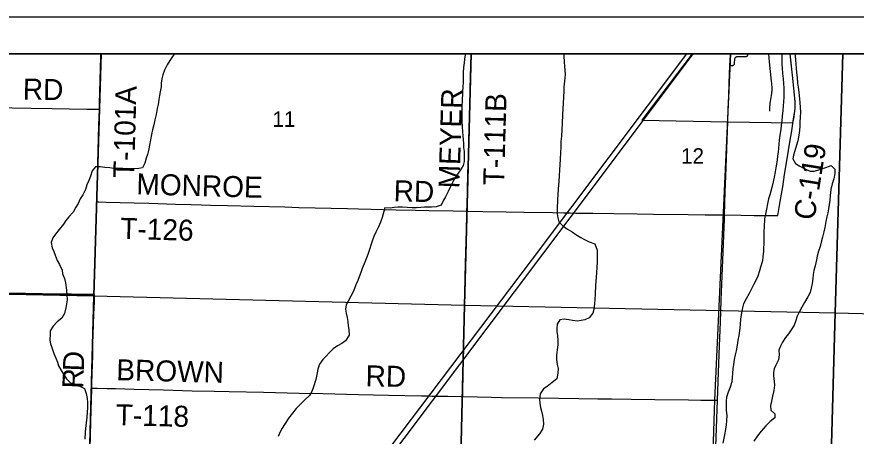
# Model space of a CAD drawing. Extents: x -38.1 to 35.9, y -2.7 to 28.5.
# Drawn here: x 19.827 to 22.099, y 18.696 to 19.831 of the extents above; entities that cross this region are included whole.
import ezdxf

# ---------------------------------------------------------------- set-up
doc = ezdxf.new("R2010")
doc.units = 0
for name, color, linetype in [('GM_X_City_Street', 7, 'Continuous'), ('GM_X_Corporation', 7, 'Continuous'), ('GM_X_Interchange_Ramps', 7, 'Continuous'), ('GM_X_Interstate_Shield', 7, 'Continuous'), ('GM_X_Major_River', 7, 'Continuous'), ('GM_X_Major_River_Text', 7, 'Continuous'), ('GM_X_Minor_Lake', 7, 'Continuous'), ('GM_X_Minor_River', 7, 'Continuous'), ('GM_X_Section', 7, 'Continuous'), ('GM_X_Township', 7, 'Continuous'), ('GM_X_US_Route', 7, 'Continuous'), ('SH_Border', 7, 'Continuous'), ('SH_Data', 7, 'Continuous')]:
    doc.layers.add(name, color=color, linetype=linetype)

msp = doc.modelspace()

# ---------------------------------------------------------------- linework, layer by layer
at = {"layer": 'GM_X_City_Street'}
for points in [[(21.7572, 19.6993), (21.7621, 19.6992), (21.7644, 19.6993), (21.7653, 19.6994), (21.7662, 19.6995), (21.7669, 19.6997), (21.7679, 19.7004), (21.7688, 19.7013), (21.7691, 19.702), (21.7694, 19.7027), (21.7696, 19.7035), (21.7698, 19.7046), (21.77, 19.7059), (21.7705, 19.7153), (21.7706, 19.7167), (21.7709, 19.7179), (21.7713, 19.7192), (21.7718, 19.7201), (21.7724, 19.721), (21.7731, 19.7217), (21.7739, 19.7223), (21.7748, 19.7227), (21.7759, 19.723), (21.7774, 19.7231), (21.7792, 19.7232), (21.7985, 19.723), (21.8007, 19.7231), (21.8015, 19.7233), (21.8025, 19.7237), (21.8033, 19.7242), (21.804, 19.7246), (21.8047, 19.7252), (21.8053, 19.7259), (21.8057, 19.7269), (21.8061, 19.7282), (21.8065, 19.7308)], [(21.8652, 19.5754), (21.8654, 19.584), (21.8656, 19.5883), (21.8659, 19.5925), (21.8664, 19.5969), (21.8672, 19.602), (21.8697, 19.6175), (21.8707, 19.6244), (21.8711, 19.6277), (21.8713, 19.6307), (21.8715, 19.6348), (21.8715, 19.6389), (21.8714, 19.6426), (21.8712, 19.646), (21.8708, 19.6514), (21.8702, 19.6565), (21.8648, 19.709), (21.8627, 19.7308)]]:
    msp.add_lwpolyline(points, dxfattribs=at)
at = {"layer": 'GM_X_Corporation'}
for points in [[(18.6101, 15.7069), (18.8445, 16.0191), (18.9897, 16.2122), (19.0483, 16.2903), (19.2337, 16.5376), (19.4121, 16.7756), (19.566, 16.98), (19.763, 17.2432), (19.9196, 17.4482), (20.1512, 17.7579), (20.6767, 18.4541), (21.2204, 19.1713), (21.641, 19.7308)], [(19.9115, 17.4163), (20.7276, 18.4937), (21.399, 19.3848), (21.6579, 19.7308)], [(25.4101, 13.4873), (25.0847, 13.9186), (24.5478, 14.5412), (23.9622, 15.2897), (23.3945, 15.9977), (22.8429, 16.6968), (22.7771, 16.7664), (22.2793, 17.0387), (22.174, 17.095), (22.1183, 17.1348), (22.0806, 17.1798), (21.9636, 17.4041), (21.7841, 17.7749), (21.744, 17.8537), (21.7155, 17.9287), (21.6978, 17.9866), (21.6921, 18.0413), (21.6956, 18.1468), (21.7163, 18.7934), (21.7602, 19.7303), (21.7602, 19.7308)]]:
    msp.add_lwpolyline(points, dxfattribs=at)
at = {"layer": 'GM_X_Interchange_Ramps'}
for points in [[(21.7572, 19.6993), (21.7587, 19.7278), (21.7589, 19.7308)], [(21.7517, 19.5463), (21.7529, 19.5801), (21.7543, 19.6171), (21.7554, 19.6512), (21.7572, 19.6993)], [(21.7427, 19.2949), (21.7447, 19.3578), (21.7463, 19.4), (21.7517, 19.5463)], [(21.7237, 18.7933), (21.7266, 18.869), (21.7291, 18.9411), (21.7315, 19.0044), (21.7337, 19.0646), (21.738, 19.1727), (21.7423, 19.2832), (21.7427, 19.2949)], [(21.7156, 18.5808), (21.7159, 18.5908), (21.72, 18.692), (21.7218, 18.7436), (21.7237, 18.7933)]]:
    msp.add_lwpolyline(points, dxfattribs=at)
at = {"layer": 'GM_X_Interstate_Shield'}
for points in [[(21.9331, 19.7308), (21.9339, 19.7255), (21.9347, 19.7137), (21.9355, 19.703), (21.9363, 19.6916), (21.9374, 19.6798), (21.9393, 19.6668), (21.9404, 19.6512), (21.942, 19.6406), (21.9439, 19.6272), (21.9447, 19.6177), (21.946, 19.6082), (21.9468, 19.5987), (21.9476, 19.5854), (21.948, 19.5736), (21.9476, 19.5592), (21.9468, 19.5459), (21.9465, 19.5349), (21.9454, 19.5232), (21.9442, 19.5103), (21.9411, 19.4956), (21.9373, 19.4832), (21.929, 19.4568), (21.9275, 19.447), (21.9344, 19.4339), (21.9467, 19.4271), (21.9601, 19.4191), (21.9748, 19.4134), (21.9858, 19.4134), (21.9954, 19.4158), (22.005, 19.4197), (22.0172, 19.4228), (22.0311, 19.4285), (22.041, 19.4183), (22.041, 19.4065), (22.0383, 19.3922), (22.0345, 19.3786), (22.0307, 19.3632), (22.029, 19.3473), (22.0279, 19.3352), (22.0264, 19.3231), (22.0242, 19.311), (22.0223, 19.3008), (22.0197, 19.2895), (22.0171, 19.277), (22.0143, 19.2612), (22.0117, 19.2491), (22.0079, 19.2348), (22.0049, 19.2246), (22.0014, 19.2092), (21.9973, 19.1971), (21.9938, 19.1836), (21.992, 19.173)], [(21.992, 19.173), (21.9881, 19.1575), (21.9847, 19.1447), (21.9828, 19.1338), (21.9814, 19.1228), (21.9798, 19.1092), (21.9776, 19.0967), (21.9746, 19.0854), (21.9685, 19.0735), (21.9593, 19.0582), (21.9521, 19.0455), (21.9449, 19.0316), (21.9392, 19.0208), (21.9346, 19.0069), (21.9313, 18.9963), (21.9253, 18.9863), (21.9158, 18.9733), (21.9079, 18.9632), (21.8992, 18.9506), (21.8939, 18.9401), (21.8898, 18.9292), (21.8902, 18.9167), (21.8886, 18.9027), (21.8818, 18.8885), (21.8773, 18.8787), (21.8751, 18.8689), (21.8752, 18.8594), (21.877, 18.8438), (21.8779, 18.8343), (21.8763, 18.8195), (21.8728, 18.8048), (21.8701, 18.7909), (21.8675, 18.7796), (21.8679, 18.767), (21.8786, 18.7572), (21.8791, 18.7458), (21.8662, 18.7359), (21.8545, 18.7245), (21.8419, 18.7101), (21.8317, 18.6971), (21.8217, 18.683)]]:
    msp.add_lwpolyline(points, dxfattribs=at)
at = {"layer": 'GM_X_Major_River'}
for points in [[(21.7572, 19.6993), (21.7587, 19.7278), (21.7589, 19.7308)], [(21.7517, 19.5463), (21.7529, 19.5801), (21.7543, 19.6171), (21.7554, 19.6512), (21.7572, 19.6993)], [(21.7427, 19.2949), (21.7447, 19.3578), (21.7463, 19.4), (21.7517, 19.5463)], [(21.7237, 18.7933), (21.7266, 18.869), (21.7291, 18.9411), (21.7315, 19.0044), (21.7337, 19.0646), (21.738, 19.1727), (21.7423, 19.2832), (21.7427, 19.2949)], [(21.7156, 18.5808), (21.7159, 18.5908), (21.72, 18.692), (21.7218, 18.7436), (21.7237, 18.7933)]]:
    msp.add_lwpolyline(points, dxfattribs=at)
at = {"layer": 'GM_X_Major_River_Text'}
for points in [[(20.0502, 19.5807), (20.0504, 19.5952), (20.0524, 19.6591), (20.0539, 19.7223), (20.0542, 19.7308)], [(21.0452, 19.3051), (21.0457, 19.3209), (21.0466, 19.3601), (21.0481, 19.4079), (21.0486, 19.4278), (21.0493, 19.4508), (21.0504, 19.4911), (21.0515, 19.534), (21.0519, 19.5551), (21.053, 19.5875), (21.0543, 19.6359), (21.0571, 19.7308)], [(21.928, 19.5429), (21.9308, 19.56), (21.9323, 19.5697), (21.933, 19.5738), (21.9334, 19.5774), (21.9337, 19.5811), (21.9339, 19.5845), (21.9341, 19.588), (21.9342, 19.5913), (21.934, 19.5957), (21.9337, 19.6001), (21.9311, 19.6283), (21.9266, 19.6726), (21.9214, 19.7217), (21.9204, 19.7308)], [(19.04, 19.5971), (19.0466, 19.597), (19.1367, 19.5954), (19.202, 19.5945), (19.2884, 19.5931), (19.3462, 19.5919), (19.3928, 19.5913), (19.44, 19.5906), (19.5121, 19.5896), (19.545, 19.5892), (19.5867, 19.5884), (19.6575, 19.5871), (19.763, 19.5854), (19.866, 19.5838), (19.9226, 19.5828), (20.0167, 19.5813), (20.0502, 19.5807)], [(20.046, 19.4319), (20.047, 19.4689), (20.0489, 19.5366), (20.0502, 19.5807)], [(21.9054, 19.4042), (21.9131, 19.4517), (21.9189, 19.4866), (21.9256, 19.5279), (21.928, 19.5429)], [(20.0433, 19.33), (20.0434, 19.3359), (20.0451, 19.4018), (20.046, 19.4319)], [(21.8873, 19.2933), (21.8936, 19.3312), (21.9001, 19.3706), (21.9054, 19.4042)], [(20.0365, 19.0787), (20.038, 19.1353), (20.0388, 19.1627), (20.0417, 19.2633), (20.0433, 19.33)], [(20.0433, 19.33), (20.0491, 19.3298), (20.0683, 19.3294), (20.1447, 19.3272), (20.1845, 19.3262), (20.2565, 19.3243), (20.2988, 19.3232), (20.3271, 19.3221), (20.3511, 19.3213), (20.3975, 19.3202), (20.4686, 19.3186), (20.5522, 19.3163)], [(20.5522, 19.3163), (20.5901, 19.3153), (20.7224, 19.3123), (20.7522, 19.3116), (20.8541, 19.309), (20.9063, 19.3079), (20.9423, 19.3071), (21.0082, 19.3059), (21.0452, 19.3051)], [(21.0369, 18.9446), (21.0377, 18.9885), (21.0387, 19.0345), (21.0398, 19.0836), (21.0418, 19.1642), (21.0433, 19.2209), (21.0449, 19.2936), (21.0452, 19.3051)], [(21.0452, 19.3051), (21.0883, 19.3041), (21.1511, 19.303), (21.2001, 19.3021), (21.2774, 19.3012), (21.3074, 19.3007), (21.3094, 19.3007)], [(21.3094, 19.3007), (21.325, 19.3003), (21.3402, 19.3), (21.3862, 19.2993), (21.443, 19.2985), (21.5064, 19.2978), (21.5506, 19.2971), (21.6444, 19.2959), (21.69, 19.2953), (21.7368, 19.295), (21.7427, 19.2949)], [(21.7427, 19.2949), (21.7879, 19.2939), (21.823, 19.2935), (21.8873, 19.2933)], [(19.0264, 19.0946), (19.0608, 19.094), (19.1089, 19.0931), (19.1611, 19.0923), (19.2574, 19.0906), (19.3562, 19.0888), (19.4326, 19.0878), (19.4767, 19.0871), (19.5587, 19.086), (19.6656, 19.0844), (19.7246, 19.0835), (19.8508, 19.0817), (19.9415, 19.0804), (19.9612, 19.08)], [(19.9612, 19.08), (19.975, 19.0797), (20.0365, 19.0787)], [(20.0289, 18.8265), (20.0292, 18.8365), (20.0302, 18.8657), (20.0311, 18.8899), (20.0318, 18.9142), (20.0323, 18.9477), (20.0331, 18.9701), (20.0339, 18.9999), (20.0349, 19.026), (20.0361, 19.0602), (20.0365, 19.0787)], [(21.0342, 18.8033), (21.0355, 18.8779), (21.0367, 18.9326), (21.0369, 18.9446)], [(20.0223, 18.5744), (20.0227, 18.5917), (20.0234, 18.6259), (20.0254, 18.6986), (20.0272, 18.7669), (20.0288, 18.8229), (20.0289, 18.8265)], [(20.0289, 18.8265), (20.0447, 18.8262), (20.0712, 18.8256), (20.0938, 18.825), (20.1447, 18.8237), (20.2236, 18.8215), (20.3013, 18.8194), (20.3614, 18.8181), (20.4019, 18.8171), (20.4943, 18.8152), (20.5914, 18.8129), (20.6555, 18.8115), (20.7519, 18.8093), (20.8334, 18.8076), (20.9219, 18.8057), (20.9401, 18.8055), (20.9514, 18.805), (20.9598, 18.8048), (20.9703, 18.8045), (20.9937, 18.8042), (21.0297, 18.8034), (21.0342, 18.8033)], [(21.0342, 18.8033), (21.0735, 18.8025), (21.112, 18.8018), (21.1393, 18.8012), (21.2381, 18.7997), (21.3481, 18.798), (21.3997, 18.7976), (21.4371, 18.7972), (21.4898, 18.7963), (21.5544, 18.7954), (21.6451, 18.7942), (21.6781, 18.7937), (21.7237, 18.7933)]]:
    msp.add_lwpolyline(points, dxfattribs=at)
at = {"layer": 'GM_X_Section'}
for points in [[(20.2537, 19.7308), (20.2485, 19.7232), (20.2406, 19.7128), (20.2334, 19.7012), (20.2262, 19.6866), (20.2223, 19.6735), (20.2198, 19.6629), (20.2179, 19.6508), (20.2172, 19.6413), (20.2153, 19.6281), (20.2135, 19.6179), (20.2113, 19.6074), (20.209, 19.5938), (20.2068, 19.5828), (20.204, 19.5666), (20.2005, 19.5523), (20.1975, 19.5383), (20.1944, 19.5251), (20.1918, 19.5123), (20.1887, 19.4976), (20.186, 19.4832), (20.1829, 19.4689), (20.1803, 19.4587), (20.1773, 19.4482), (20.1735, 19.435), (20.1667, 19.4219), (20.1567, 19.4203), (20.1446, 19.4199), (20.1343, 19.4195), (20.1248, 19.4198), (20.1138, 19.4205), (20.1002, 19.4216), (20.0884, 19.4208), (20.0782, 19.4219), (20.0649, 19.4234), (20.0528, 19.4249), (20.0399, 19.4253), (20.0308, 19.4142), (20.0266, 19.3995), (20.0213, 19.3879), (20.0164, 19.3759), (20.0126, 19.3635), (20.0054, 19.3496), (19.9982, 19.3381), (19.9925, 19.3257), (19.9869, 19.316), (19.9789, 19.3026), (19.9675, 19.2896), (19.9596, 19.2796), (19.9529, 19.2699), (19.9418, 19.2558), (19.9316, 19.2432), (19.9241, 19.2332), (19.9199, 19.2201), (19.9221, 19.206), (19.9271, 19.1956), (19.931, 19.186), (19.9363, 19.1714), (19.9421, 19.1606), (19.9492, 19.1452), (19.9508, 19.1357), (19.9557, 19.1226)], [(21.0402, 19.7308), (21.0402, 19.7278), (21.0391, 19.7164), (21.0381, 19.7066), (21.0361, 19.6933), (21.0354, 19.6801), (21.035, 19.6691), (21.035, 19.6539), (21.0338, 19.6414), (21.0331, 19.6278), (21.0323, 19.6012), (21.0316, 19.5906), (21.0312, 19.5781), (21.0319, 19.5485), (21.0326, 19.534), (21.0337, 19.52), (21.0345, 19.5085), (21.0353, 19.499), (21.0362, 19.4884), (21.0362, 19.477), (21.0374, 19.4667), (21.0382, 19.4534), (21.0378, 19.4397), (21.0351, 19.4281), (21.026, 19.4139), (21.0173, 19.4016), (21.0101, 19.3897), (21.0012, 19.3721), (20.9947, 19.3583), (20.9875, 19.344), (20.9818, 19.3343), (20.9754, 19.3209), (20.962, 19.3167), (20.9494, 19.3159), (20.9399, 19.3162), (20.9304, 19.3157), (20.9201, 19.3149), (20.9087, 19.3137), (20.8973, 19.3137), (20.8833, 19.3148), (20.8708, 19.316), (20.8579, 19.316), (20.848, 19.3151), (20.8373, 19.3135), (20.8232, 19.3139), (20.8156, 19.2876), (20.8111, 19.2748), (20.8058, 19.2624), (20.7989, 19.2478), (20.7936, 19.2362), (20.7895, 19.2261), (20.7858, 19.2156), (20.7812, 19.2013), (20.7773, 19.1877), (20.7728, 19.1757), (20.7667, 19.1622), (20.7618, 19.1502), (20.7581, 19.1394), (20.7539, 19.1277), (20.7502, 19.1176), (20.7449, 19.106), (20.7379, 19.0887), (20.7235, 19.0618), (20.7182, 19.0513), (20.7168, 19.04), (20.7187, 19.0289), (20.7214, 19.0171), (20.723, 19.0064), (20.7241, 18.9946), (20.7254, 18.9851), (20.7265, 18.9699), (20.7169, 18.9538), (20.7064, 18.9469), (20.6948, 18.9404), (20.6836, 18.9328), (20.6726, 18.9221), (20.6647, 18.9125), (20.655, 18.9033), (20.6463, 18.8914), (20.6413, 18.8775), (20.6399, 18.8677), (20.6363, 18.8496), (20.6295, 18.827), (20.6254, 18.8169), (20.6187, 18.8068)], [(21.3081, 19.7308), (21.3079, 19.7242), (21.3085, 19.7086), (21.3097, 19.6964), (21.3105, 19.6861), (21.311, 19.6747), (21.3093, 19.6569), (21.308, 19.6403), (21.3074, 19.63), (21.3069, 19.6145), (21.306, 19.5963), (21.3052, 19.5823), (21.3039, 19.5656), (21.3033, 19.5432), (21.302, 19.5251), (21.3011, 19.5076), (21.2999, 19.4936), (21.2995, 19.4781), (21.2983, 19.4633), (21.2974, 19.4455), (21.2969, 19.4299), (21.2957, 19.4171), (21.2949, 19.4008), (21.2937, 19.3852), (21.2919, 19.3655), (21.2911, 19.35), (21.2903, 19.336), (21.2896, 19.3113), (21.2896, 19.2977), (21.2911, 19.2866), (21.2942, 19.2759), (21.3049, 19.265), (21.3176, 19.2562), (21.3299, 19.2487), (21.34, 19.2423), (21.3538, 19.2339), (21.3635, 19.2283), (21.3758, 19.2219), (21.3912, 19.2162), (21.398, 19.1996), (21.3982, 19.1841), (21.3981, 19.1677), (21.3973, 19.1522), (21.3961, 19.1386), (21.3954, 19.1265), (21.3943, 19.1147), (21.3936, 19.1045), (21.3929, 19.0806), (21.3917, 19.0658), (21.3906, 19.0549), (21.3886, 19.0394), (21.3864, 19.0292), (21.3766, 19.0162), (21.3646, 19.0112), (21.3543, 19.0089), (21.3444, 19.0076), (21.3308, 19.0088), (21.321, 19.0113), (21.3089, 19.0132), (21.2967, 19.0113), (21.2895, 18.9994), (21.2888, 18.9887), (21.2889, 18.9785), (21.2901, 18.9686), (21.2912, 18.9538), (21.2912, 18.9435), (21.2893, 18.9299), (21.2874, 18.9155), (21.2874, 18.9034), (21.2897, 18.8904), (21.292, 18.8797), (21.2913, 18.8672), (21.2889, 18.8517), (21.276, 18.8411), (21.2621, 18.8309), (21.2524, 18.824), (21.2432, 18.8106), (21.242, 18.7954), (21.2425, 18.7859), (21.2448, 18.7741), (21.2476, 18.7638), (21.2495, 18.7519), (21.2518, 18.7412), (21.2526, 18.7291), (21.2495, 18.7151), (21.2419, 18.7024), (21.2274, 18.6858)], [(21.8976, 19.7308), (21.8975, 19.7276), (21.8977, 19.7109), (21.8978, 19.7014), (21.8983, 19.6919), (21.8994, 19.6775), (21.9013, 19.6634), (21.9024, 19.6504), (21.9032, 19.6375), (21.9036, 19.6257), (21.9028, 19.6132), (21.9021, 19.6007), (21.9018, 19.5901), (21.9002, 19.5769), (21.8983, 19.5621), (21.8975, 19.5504), (21.8964, 19.5375), (21.8949, 19.5258), (21.8926, 19.5106), (21.891, 19.4974), (21.89, 19.4864), (21.8889, 19.4751), (21.8878, 19.4645), (21.8863, 19.4543), (21.8853, 19.4433), (21.8834, 19.4331), (21.8816, 19.4218), (21.8801, 19.4112), (21.8774, 19.3968), (21.8748, 19.384), (21.8705, 19.3693), (21.868, 19.3591), (21.865, 19.3493), (21.862, 19.338), (21.8594, 19.3252), (21.8563, 19.3101), (21.8532, 19.2965), (21.8509, 19.2845), (21.8503, 19.2625), (21.8495, 19.25), (21.8492, 19.2401), (21.8492, 19.2257), (21.8483, 19.1969), (21.8468, 19.1817), (21.8457, 19.1704), (21.8398, 19.1531), (21.8373, 19.1433), (21.8327, 19.129), (21.827, 19.1174), (21.821, 19.1054), (21.8161, 19.0953), (21.8093, 19.0826), (21.8016, 19.068), (21.7944, 19.0546), (21.7914, 19.0433), (21.7878, 19.0251), (21.7863, 19.0127), (21.7848, 18.999), (21.7837, 18.9884), (21.7812, 18.9688), (21.7785, 18.9556), (21.7766, 18.9427), (21.7739, 18.9269), (21.7713, 18.9167), (21.769, 18.9038), (21.7667, 18.8906), (21.7656, 18.8785), (21.7645, 18.8656), (21.7634, 18.855), (21.7623, 18.8437), (21.7577, 18.8286), (21.7527, 18.8155), (21.7482, 18.802), (21.7471, 18.791), (21.7467, 18.78), (21.7475, 18.7659), (21.7486, 18.7522), (21.7482, 18.7378), (21.7471, 18.7272), (21.7456, 18.7151), (21.7434, 18.7042), (21.738, 18.677)], [(19.9557, 19.1226), (19.9588, 19.1111), (19.9609, 19.091), (19.962, 19.078), (19.9628, 19.0651), (19.9613, 19.0545), (19.9591, 19.0436), (19.956, 19.0285), (19.9488, 19.0158), (19.9363, 19.0052), (19.925, 18.9941), (19.9174, 18.9814), (19.9167, 18.9716), (19.9166, 18.956), (19.9182, 18.9465), (19.9214, 18.9362), (19.9266, 18.9197), (19.9323, 18.907), (19.9369, 18.8966), (19.94, 18.8867), (19.9461, 18.8755), (19.9545, 18.8619), (19.9614, 18.8515), (19.9717, 18.8406), (19.9855, 18.8333), (19.9977, 18.8318), (20.01, 18.8254), (20.0145, 18.812), (20.0168, 18.7979), (20.018, 18.7872), (20.0179, 18.7732), (20.0176, 18.761), (20.0164, 18.7478), (20.0145, 18.7323), (20.0129, 18.7168), (20.0122, 18.7073), (20.0105, 18.688)], [(20.6187, 18.8068), (20.6066, 18.7946), (20.5956, 18.7836), (20.5831, 18.7714), (20.5732, 18.7584), (20.5633, 18.7458), (20.5514, 18.7283), (20.545, 18.7179), (20.5398, 18.7082), (20.5341, 18.6958)]]:
    msp.add_lwpolyline(points, dxfattribs=at)
at = {"layer": 'GM_X_US_Route'}
for points in [[(25.4101, 19.7308), (18.6101, 19.7308)], [(20.0232, 18.6265), (20.0252, 18.6991), (20.027, 18.7675), (20.0286, 18.8234), (20.0287, 18.827), (20.029, 18.8371), (20.0299, 18.8663), (20.0309, 18.8905), (20.0315, 18.9147), (20.0321, 18.9483), (20.0329, 18.9706), (20.0337, 19.0004), (20.0347, 19.0265), (20.0358, 19.0607), (20.0362, 19.0793), (19.9748, 19.0802), (19.9412, 19.0809), (19.8505, 19.0822), (19.7244, 19.084)], [(19.7244, 19.084), (19.8505, 19.0822), (19.9412, 19.0809), (19.9748, 19.0802), (20.0362, 19.0793), (20.0358, 19.0607), (20.0347, 19.0265), (20.0337, 19.0004), (20.0329, 18.9706), (20.0321, 18.9483), (20.0315, 18.9147), (20.0309, 18.8905), (20.0299, 18.8663), (20.029, 18.8371), (20.0287, 18.827), (20.0286, 18.8234), (20.027, 18.7675), (20.0252, 18.6991), (20.0232, 18.6265)]]:
    msp.add_lwpolyline(points, dxfattribs=at)
for points in [[(20.0554, 19.7308), (19.0472, 19.7308), (19.0268, 19.0959), (20.0353, 19.0758)], [(21.057, 19.7308), (20.0554, 19.7308), (20.0353, 19.0758), (21.0384, 19.0503)], [(22.0631, 19.7308), (21.057, 19.7308), (21.0384, 19.0503), (22.0424, 19.0296)], [(21.9202, 19.7308), (21.6549, 19.7308), (21.5192, 19.5511), (21.7515, 19.5468), (21.9277, 19.5435), (21.9305, 19.5606), (21.9321, 19.5703), (21.9328, 19.5744), (21.9332, 19.5779), (21.9335, 19.5816), (21.9337, 19.585), (21.9339, 19.5885), (21.934, 19.5919), (21.9338, 19.5962), (21.9335, 19.6007), (21.9309, 19.6289), (21.9263, 19.6731), (21.9211, 19.7222)], [(23.1141, 19.7308), (22.0631, 19.7308), (22.0424, 19.0296), (23.1004, 19.0039)], [(19.0268, 19.0959), (20.0353, 19.0758), (20.0086, 18.0758), (18.9989, 18.0871)], [(20.0353, 19.0758), (21.0384, 19.0503), (21.0147, 18.0482), (20.0086, 18.0758)], [(21.0384, 19.0503), (22.0424, 19.0296), (22.0145, 18.0265), (21.0147, 18.0482)], [(23.1004, 19.0039), (23.0833, 18.0071), (22.0145, 18.0265), (22.0424, 19.0296)]]:
    msp.add_lwpolyline(points, close=True, dxfattribs=at)
at = {"layer": 'SH_Border'}
msp.add_line((18.6101, 19.7308), (25.4101, 19.7308), dxfattribs=at)
at = {"layer": 'SH_Data'}
msp.add_line((18.5101, 19.8308), (25.5101, 19.8308), dxfattribs=at)

# ---------------------------------------------------------------- texts
at = {"layer": 'GM_X_Minor_Lake'}
for s, height, rotation, p in [('RD', 0.05682, 359.0154, (19.8426, 19.607)), ('T-101A', 0.05682, 88.4854, (20.1444, 19.3941)), ('MEYER', 0.05682, 88.2394, (21.0249, 19.366)), ('T-111B', 0.05682, 88.4774, (21.146, 19.3744)), ('MONROE', 0.05682, 358.4171, (20.1499, 19.3504)), ('RD', 0.05682, 358.5189, (20.8464, 19.332)), ('T-126', 0.05682, 358.3107, (20.1062, 19.2304)), ('D', 0.0568, 87.8813, (20.008, 18.871)), ('BROWN', 0.05682, 358.5261, (20.0956, 18.8479)), ('RD', 0.05682, 359.0272, (20.7706, 18.8312)), ('R', 0.0568, 88.4034, (20.0067, 18.8245)), ('T-118', 0.05682, 358.5963, (20.094, 18.7261))]:
    msp.add_text(s, height=height, rotation=rotation, dxfattribs=at).set_placement(p)
at = {"layer": 'GM_X_Minor_River'}
for s, p in [('11', (20.5186, 19.5331)), ('12', (21.6249, 19.4334))]:
    msp.add_text(s, height=0.04186, rotation=0, dxfattribs=at).set_placement(p)
at = {"layer": 'GM_X_Township'}
msp.add_text('C-119', height=0.05682, rotation=80.8992, dxfattribs=at).set_placement((21.9857, 19.2784))

doc.saveas('drawing.dxf')
